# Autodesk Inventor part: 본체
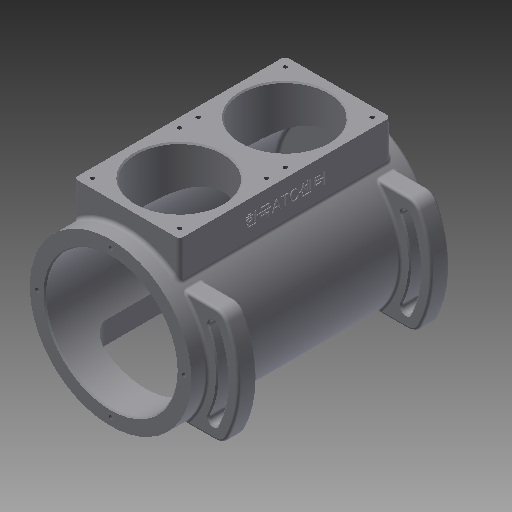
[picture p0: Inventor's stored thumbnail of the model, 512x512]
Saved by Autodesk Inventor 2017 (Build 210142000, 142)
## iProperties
Created: 2016-11
Part Number: 본체
Material: 일반
Document SubType Name: Modeling
Designer: mduedu
Density: 1 g/cm^3
Appearance: 기본값
Author: mduedu
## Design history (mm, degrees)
sketch "스케치1"
  geometry: C1 r 65 at (0, 0); 1 further point
  constraints: 1 centre point, 1 coincident
  dimensions: "d119" = 130 diameter of C1
extrude "돌출1" new body sketch "스케치1" distance "d3" = 98; taper "d4" = 0 deg; dims "d132" = 97, "d133" = 0
feature "쉘1" dims "d120" = 12, "d134" = 8
node "작업 평면2"
sketch "스케치13"
  geometry: L1 (42.5, 85)-(-42.5, 85); L2 (-42.5, 85)-(-42.5, -85); L3 (-42.5, -85)-(42.5, -85); L4 (42.5, -85)-(42.5, 85); 2 further points
  constraints: 8 end point, 2 parallel, 1 horizontal, 1 midpoint, 1 perpendicular, 1 vertical alignment
  dimensions: "d122" = 170 distance of L1.end L2.end; "d124" = 85 distance of L2.end L3.end; "d125" = 85 distance from line of point (0, 0) L1 (= 0.5 x d122)
extrude "돌출11" join sketch "스케치13" stored distance "d126" = 10; taper "d127" = 0 deg
sketch "스케치14"
  geometry: L1 (65, 97)-(-65, 97) reference; C1 r 35 at (0, 42.5); 1 further point
  constraints: 1 centre point, 1 vertical alignment
  dimensions: "d128" = 70 diameter of C1; "d129" = 54.5 distance from line of C1.centre L1
extrude "돌출12" cut sketch "스케치14" stored distance "d130" = 10; taper "d131" = 0 deg
sketch "스케치15"
  geometry: C1 r 53 at (0, 0) reference; 1 further point
extrude "돌출13" cut sketch "스케치15" stored distance "d135" = 10; taper "d136" = 0 deg
chamfer "모따기1" distance "d54" = 1; stored, may be unused: second distance "d55" = 2, angle "d56" = 45 deg
sketch "스케치8"
  geometry: C1 r 30 at (0, 0); C2 r 65 at (0, 0) reference; 1 further point
  constraints: 1 centre point, 1 concentric
  dimensions: "d57" = 60 diameter of C1
extrude "돌출8" join sketch "스케치8" distance "d58" = 14; taper "d59" = 0 deg
hole "구멍3" diameter "d62" = 41; stored, may be unused: countersink angle "d66" = 90 deg, drill point angle "d68" = 0 deg; dims "d63" = 6, "d64" = 47, "d65" = 14, "d67" = 17, "d195" = 10, "d196" = 10
fillet "모깎기11" dims "d69" = 3
fillet "모깎기12" dims "d70" = 3
fillet "모깎기13" dims "d71" = 0.3
chamfer "모따기2" distance "d72" = 1; stored, may be unused: second distance "d73" = 2, angle "d74" = 45 deg
node "작업 평면3"
sketch "스케치16"
  geometry: L1 (-42.5, -80)-(47.5, -80); L2 (-42.5, -80)-(21.14, -16.36); L3 (-42.5, -80)-(21.14, -143.64); L4 (3.462, -34.038)-(34.879, -34.038); L5 (3.462, -125.962)-(34.879, -125.962); A1 r 65 centre (-42.5, -80) between (3.462, -34.038) and (3.462, -125.962) reference; A2 r 90 centre (-42.5, -80) between (34.879, -125.962) and (34.879, -34.038); A3 r 90 centre (-42.5, -80) between (34.879, -34.038) and (34.879, -125.962); A4 r 65 centre (-42.5, -80) between (3.462, -125.962) and (3.462, -34.038); 1 further point
  constraints: 11 point on circle, 10 end point, 3 centre point, 2 parallel, 2 point on line, 1 coincident, 1 horizontal
  dimensions: "d140" = 45 deg angle of L3 L1; "d141" = 45 deg angle of L2 L1; "d142" = 25 radial gap between concentric circles of A1 A2
extrude "돌출14" join sketch "스케치16" distance "d143" = 15; taper "d144" = 0 deg
sketch "스케치17"
  geometry: L1 (-42.5, -80)-(34.414, -80); L2 (-42.5, -80)-(27.208, -47.495); L3 (-42.5, -80)-(27.208, -112.505); L4 (34.879, -34.038)-(3.462, -34.038) reference; L5 (3.462, -125.962)-(34.879, -125.962) reference; A1 r 65 centre (-42.5, -80) between (3.462, -34.038) and (3.462, -125.962) reference; A2 r 76.914 centre (-42.5, -80) between (19.17, -125.962) and (19.17, -34.038); A3 r 4 centre (27.208, -47.495) between (23.582, -49.185) and (30.833, -45.804); A4 r 4 centre (27.208, -112.505) between (30.833, -114.196) and (23.582, -110.815); A5 r 80.914 centre (-42.5, -80) between (30.833, -114.196) and (30.833, -45.804); A6 r 72.914 centre (-42.5, -80) between (23.582, -110.815) and (23.582, -49.185); 1 further point
  constraints: 13 point on circle, 6 end point, 5 centre point, 5 coincident, 3 midpoint, 2 point on line, 1 equal radius, 1 horizontal
  dimensions: "d145" = 25 deg angle of L1 L3; "d146" = 25 deg angle of L2 L1; "d147" = 8 diameter of A3
extrude "돌출15" cut sketch "스케치17" stored distance "d150" = 15; taper "d151" = 0 deg
fillet "모깎기17" dims "d152" = 10
fillet "모깎기18" dims "d153" = 2
fillet "모깎기19" dims "d154" = 2
chamfer "모따기4" distance "d155" = 1; stored, may be unused: second distance "d156" = 2, angle "d157" = 45 deg
fillet "모깎기20" dims "d159" = 3
fillet "모깎기21" dims "d160" = 3
fillet "모깎기22" dims "d161" = 3
node "작업 평면4"
sketch "스케치18"
  geometry: L1 (-42.5, 70)-(42.5, 70); L2 (42.5, 70)-(42.5, -70); L3 (42.5, -70)-(-42.5, -70); L4 (-42.5, -70)-(-42.5, 70); 2 further points
  constraints: 8 end point, 2 parallel, 1 horizontal, 1 midpoint, 1 perpendicular, 1 vertical alignment
  dimensions: "d162" = 140 distance of L1.end L2.end; "d164" = 85 distance of L2.end L3.end; "d165" = 70 distance from line of point (0, 0) L1 (= 0.5 x d162)
extrude "돌출16" cut sketch "스케치18" stored distance "d166" = 15; taper "d167" = 0 deg
fillet "모깎기23" dims "d168" = 10
fillet "모깎기24" dims "d173" = 3
sketch "스케치19"
  geometry: 4 further points
  constraints: 4 other
hole "구멍6" sketch "스케치19" at (0, -59), (59, 0), (-59, 0), (0, 59) diameter "d174" = 3.242; stored, may be unused: countersink angle "d178" = 90 deg, drill point angle "d180" = 120 deg; dims "d175" = 8, "d176" = 4, "d177" = 2, "d179" = 10
sketch "스케치20"
  geometry: L1 (35, -77.5)-(-35, -77.5); L2 (-35, -77.5)-(-35, -7.5); L3 (-35, -7.5)-(35, -7.5); L4 (35, -7.5)-(35, -77.5); L5 (35, -77.5)-(-35, -7.5); L6 (-35, -77.5)-(35, -7.5); C1 r 36 at (0, -42.5) reference; 5 further points
  constraints: 12 end point, 4 coincident, 2 midpoint, 2 parallel, 1 horizontal, 1 perpendicular
  dimensions: "d181" = 70 distance of L2.end L3.end; "d182" = 70 distance of L1.end L2.end
hole "구멍7" sketch "스케치20" at (-35, -77.5), (-35, -7.5), (35, -7.5), (35, -77.5) diameter "d183" = 3.242; stored, may be unused: countersink angle "d187" = 90 deg, drill point angle "d189" = 118 deg; dims "d184" = 8, "d185" = 4, "d186" = 2, "d188" = 10
sketch "스케치21"
  geometry: L1 (164, 0)-(0, 0) reference; L2 (-3, 0)-(-3, -24.649) reference; 3 further points
  constraints: 1 midpoint, 1 vertical alignment, 1 other
  dimensions: "d190" = 15 distance from line of point (82, -15) L1; "d191" = 85 distance from line of point (82, 0) L2 (derived)
feature "엠보싱2" sketch "스케치21" dims "d3" = 98, "d4" = 0, "d119" = 130, "d132" = 97, "d133" = 0, "d192" = 0.5, "d193" = 0
node "솔리드1"
mirror "대칭5"
mirror "대칭6"
mirror "대칭7"
